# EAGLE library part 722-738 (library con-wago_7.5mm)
Serie 722, Federleiste mit geraden Einlötstiften / Series 722, Female connector with straight solder pins Polzahl / Pole No.: 8 Rastermaß / Pitch: 7.5 mm Bemessungsspannung / Rated Voltage: 630 V Nennstrom / Nominal Current: 12 A Lötstiftlänge: / Solder Pin Length: 5 mm Farbe / Color: lichtgrau / light gray Stand: 01.01.2012. Die jeweils aktuellen Daten zu diesem Artikel finden Sie in unserem Produktkatalog, den Sie unter www.wago.com einsehen können. As of: 01/01/2012. Please find the newest data for this article in our product catalogue, which can be viewed under www.wago.com.
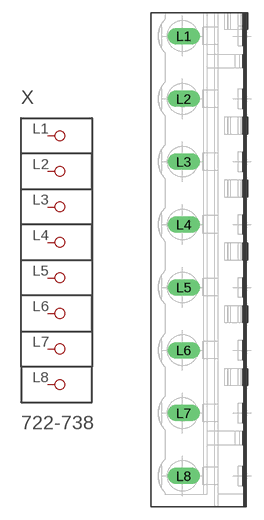
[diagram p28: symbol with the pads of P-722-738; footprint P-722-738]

Designator prefix X

## 722-738  [P-722-738]
L1  P1
L2  P2
L3  P3
L4  P4
L5  P5
L6  P6
L7  P7
L8  P8

## Footprint P-722-738 (pad centres in mm)
drill 1.3 long: L1 -2.056,26.7; L2 -2.056,19.2; L3 -2.056,11.7; L4 -2.056,4.2; L5 -2.056,-3.3; L6 -2.056,-10.8; L7 -2.056,-18.3; L8 -2.056,-25.8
